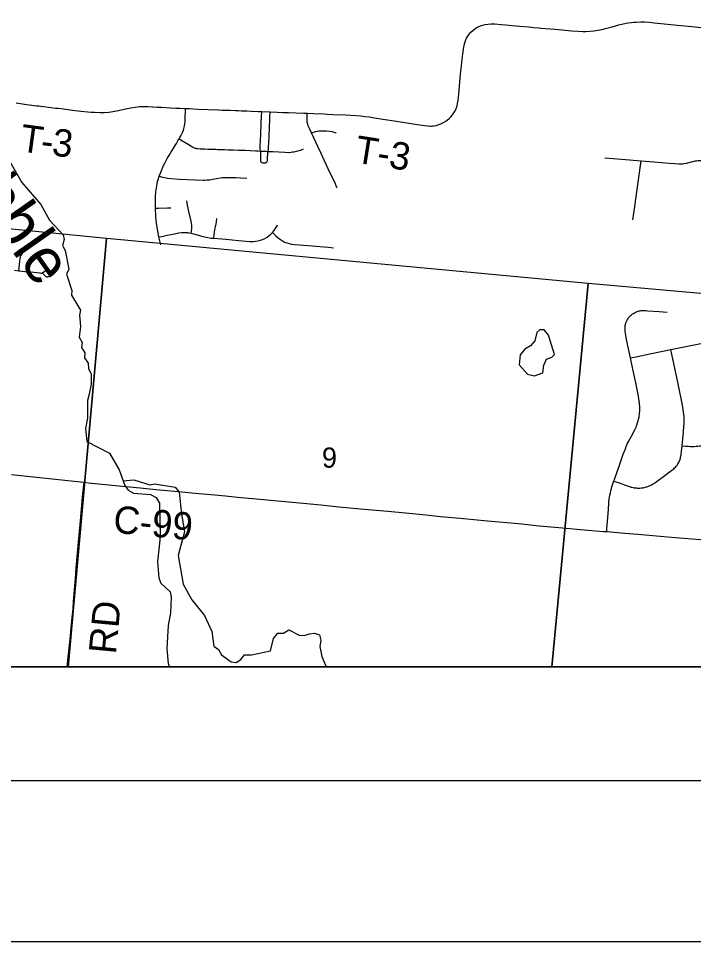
# Model space of a CAD drawing. Extents: x 0 to 1134, y 0 to 440.
# Drawn here: x 288.4 to 330.5, y 0 to 57.5 of the extents above; entities that cross this region are included whole.
import ezdxf

# ---------------------------------------------------------------- set-up
doc = ezdxf.new("R2010")
doc.units = 0
for name, color, linetype in [('GM_X_City_Street', 7, 'Continuous'), ('GM_X_County_Road', 7, 'Continuous'), ('GM_X_County_Road_Text', 7, 'Continuous'), ('GM_X_Major_River', 7, 'Continuous'), ('GM_X_Minor_Lake', 7, 'Continuous'), ('GM_X_Minor_River', 7, 'Continuous'), ('GM_X_Minor_River_Text', 7, 'Continuous'), ('GM_X_Section_Text', 7, 'Continuous'), ('GM_X_Township_Road', 7, 'Continuous'), ('GM_X_Township_Road_Text', 7, 'Continuous'), ('GM_X_Unincorporated', 7, 'Continuous'), ('SH_Border', 7, 'Continuous'), ('SH_Cut_Line', 7, 'Continuous'), ('SH_Text', 7, 'Continuous')]:
    doc.layers.add(name, color=color, linetype=linetype)

msp = doc.modelspace()

# ---------------------------------------------------------------- linework, layer by layer
at = {"layer": 'GM_X_City_Street'}
for points in [[(297.296, 43.386), (297.25, 43.555), (297.208, 43.71), (297.172, 43.877), (297.147, 43.99), (297.098, 44.268), (297.048, 44.598), (297.013, 44.899), (296.989, 45.15), (296.966, 45.661), (296.957, 45.995), (296.96, 46.214), (296.966, 46.389), (296.986, 46.684), (297.016, 46.947), (297.06, 47.193), (297.092, 47.327), (297.124, 47.453), (297.197, 47.669), (297.247, 47.8), (297.29, 47.912), (297.346, 48.055), (297.413, 48.215), (297.469, 48.335), (297.536, 48.47), (297.606, 48.607), (297.688, 48.759), (297.749, 48.858), (297.808, 48.958), (297.875, 49.063), (297.919, 49.133), (298, 49.27), (298.185, 49.571), (298.263, 49.708), (298.38, 49.898), (298.431, 49.981), (298.485, 50.071), (298.544, 50.179), (298.588, 50.267), (298.646, 50.386), (298.702, 50.538), (298.728, 50.632), (298.749, 50.708), (298.769, 50.807), (298.786, 50.907), (298.805, 51.073), (298.813, 51.213), (298.818, 51.35), (298.821, 51.727), (298.823, 51.882)], [(303.495, 49.225), (303.487, 49.352), (303.487, 49.463), (303.506, 49.978), (303.517, 50.216), (303.521, 50.335), (303.526, 50.446), (303.535, 50.767), (303.541, 50.896), (303.549, 51.079), (303.553, 51.163), (303.558, 51.225), (303.565, 51.388), (303.577, 51.687)], [(303.971, 49.209), (303.997, 49.355), (304.002, 49.402), (304.006, 49.466), (304.01, 49.559), (304.015, 49.673), (304.021, 49.799), (304.034, 50.042), (304.051, 50.345), (304.058, 50.484), (304.063, 50.607), (304.067, 50.731), (304.071, 50.884), (304.074, 50.998), (304.084, 51.217), (304.091, 51.382), (304.095, 51.666)], [(308.278, 46.934), (308.264, 46.968), (308.105, 47.328), (307.831, 47.901), (307.272, 49.082), (307.064, 49.52), (306.675, 50.353), (306.566, 50.586), (306.481, 50.79), (306.441, 50.912), (306.415, 51.036), (306.403, 51.164), (306.404, 51.329), (306.404, 51.579)], [(306.675, 50.353), (306.956, 50.442), (307.045, 50.47), (307.137, 50.486), (307.249, 50.492), (307.399, 50.492), (307.606, 50.484), (307.83, 50.464), (307.959, 50.442), (308.067, 50.409), (308.187, 50.357), (308.221, 50.34)], [(298.431, 49.981), (298.509, 49.939), (298.605, 49.888), (298.988, 49.648), (299.222, 49.51), (299.314, 49.46), (299.38, 49.431), (299.425, 49.413), (299.474, 49.401), (299.526, 49.391), (299.602, 49.381), (299.748, 49.369), (299.886, 49.364), (300.025, 49.359), (300.212, 49.354), (300.343, 49.349), (300.457, 49.347), (300.573, 49.342), (300.728, 49.337), (300.844, 49.334), (301.017, 49.329), (301.269, 49.317), (301.484, 49.31), (301.822, 49.3), (302.126, 49.29), (302.55, 49.273), (302.866, 49.258), (303.194, 49.24), (303.341, 49.233), (303.495, 49.225), (303.632, 49.221), (303.857, 49.213), (303.971, 49.209), (304.276, 49.194), (305.02, 49.152), (305.243, 49.148), (305.409, 49.159), (305.496, 49.169), (305.59, 49.184), (305.752, 49.214), (305.859, 49.241), (305.996, 49.29), (306.047, 49.309), (306.18, 49.367)], [(303.495, 49.225), (303.501, 49.152), (303.505, 49.073), (303.503, 48.977), (303.499, 48.849), (303.497, 48.774), (303.494, 48.697), (303.494, 48.63), (303.497, 48.603), (303.503, 48.584), (303.516, 48.564), (303.53, 48.549), (303.549, 48.532), (303.566, 48.523), (303.599, 48.508), (303.642, 48.496), (303.68, 48.492), (303.726, 48.489), (303.77, 48.492), (303.798, 48.495), (303.829, 48.503), (303.86, 48.519), (303.887, 48.538), (303.916, 48.578), (303.926, 48.607), (303.93, 48.636), (303.938, 48.747), (303.953, 49.089), (303.956, 49.13), (303.962, 49.171), (303.971, 49.209)], [(297.197, 47.669), (297.393, 47.608), (297.531, 47.572), (297.62, 47.552), (297.719, 47.536), (297.941, 47.515), (298.461, 47.486), (299.428, 47.444), (299.931, 47.425), (300.03, 47.423), (300.154, 47.427), (300.339, 47.443), (300.542, 47.474), (300.998, 47.563), (301.127, 47.58), (301.222, 47.586), (301.35, 47.591), (301.946, 47.579), (302.262, 47.566), (302.647, 47.547)], [(299.188, 44.113), (299.21, 44.253), (299.228, 44.38), (299.231, 44.437), (299.23, 44.489), (299.218, 44.617), (299.179, 44.855), (299.066, 45.384), (298.965, 45.861), (298.908, 46.135)], [(296.966, 45.661), (297.153, 45.666), (297.708, 45.683), (297.913, 45.687)], [(300.603, 43.797), (300.619, 44.007), (300.632, 44.177), (300.658, 44.345), (300.698, 44.508), (300.749, 44.705), (300.767, 44.812), (300.779, 45.018)], [(297.172, 43.877), (297.349, 43.915), (297.691, 43.987), (298.148, 44.083), (298.386, 44.127), (298.58, 44.155), (298.724, 44.165), (298.846, 44.163), (298.957, 44.155), (299.022, 44.144), (299.188, 44.113), (299.335, 44.074), (299.853, 43.921), (300.014, 43.88), (300.112, 43.858), (300.231, 43.837), (300.415, 43.813), (300.603, 43.797), (301.343, 43.735), (302.142, 43.663), (302.86, 43.602), (302.971, 43.597), (303.067, 43.598), (303.195, 43.608), (303.339, 43.633), (303.499, 43.675), (303.637, 43.725), (303.769, 43.788), (303.911, 43.873), (304.045, 43.969), (304.143, 44.052), (304.253, 44.165), (304.352, 44.284), (304.463, 44.45), (304.533, 44.568), (304.566, 44.638)], [(304.253, 44.165), (304.396, 44.019), (304.46, 43.952), (304.627, 43.804), (304.745, 43.714), (304.871, 43.634), (305.002, 43.564), (305.14, 43.509), (305.283, 43.467), (305.357, 43.449), (305.429, 43.438), (305.614, 43.416), (306.466, 43.342), (307.208, 43.28), (307.745, 43.233), (308.059, 43.204)], [(288.449, 41.771), (288.47, 41.948), (288.492, 42.175), (288.528, 42.506), (288.538, 42.573), (288.544, 42.616), (288.561, 42.67), (288.582, 42.716), (288.606, 42.752), (288.641, 42.795), (288.687, 42.854), (288.704, 42.887), (288.713, 42.923), (288.714, 42.96), (288.708, 42.997), (288.693, 43.031), (288.67, 43.06), (288.639, 43.081), (288.604, 43.092), (288.566, 43.095), (288.524, 43.088), (288.496, 43.074), (288.467, 43.05), (288.446, 43.019), (288.438, 43.002), (288.432, 42.947), (288.436, 42.922), (288.447, 42.893), (288.47, 42.856), (288.498, 42.82), (288.568, 42.738)], [(288.175, 41.801), (288.449, 41.771), (288.508, 41.765), (288.971, 41.712), (289.38, 41.676), (289.749, 41.638), (289.826, 41.63), (289.878, 41.623), (289.904, 41.618), (289.935, 41.605), (289.961, 41.587), (290.011, 41.532), (290.061, 41.474), (290.1, 41.437), (290.138, 41.414), (290.155, 41.406), (290.179, 41.399), (290.211, 41.395), (290.231, 41.395), (290.254, 41.398), (290.283, 41.408), (290.306, 41.419), (290.33, 41.434), (290.352, 41.45), (290.372, 41.47), (290.391, 41.49), (290.41, 41.522), (290.422, 41.557), (290.425, 41.594), (290.422, 41.622), (290.417, 41.649), (290.402, 41.683), (290.391, 41.7), (290.354, 41.74), (290.328, 41.756), (290.306, 41.767), (290.28, 41.776), (290.252, 41.78), (290.222, 41.782), (290.196, 41.778), (290.171, 41.77), (290.136, 41.756), (290.104, 41.74), (289.912, 41.633)]]:
    msp.add_lwpolyline(points, dxfattribs=at)
at = {"layer": 'GM_X_County_Road'}
for points in [[(287.992, 29.088), (292.286, 28.631), (292.517, 28.602)], [(292.517, 28.602), (292.78, 28.572), (294.467, 28.399), (296.008, 28.26), (296.991, 28.161), (297.695, 28.096), (298.382, 28.035), (299.66, 27.91), (300.661, 27.816), (301.328, 27.751), (302.07, 27.681), (303.239, 27.575), (306.152, 27.296), (307.265, 27.19), (308.378, 27.081), (309.733, 26.953), (311.44, 26.796), (313.408, 26.612), (314.168, 26.53), (314.71, 26.475), (315.947, 26.362), (317.633, 26.202), (319.58, 26.026), (320.859, 25.898), (322.083, 25.783), (323.902, 25.621), (324.868, 25.544), (325.072, 25.526)], [(325.072, 25.526), (326.204, 25.427), (327.003, 25.369), (328.396, 25.254), (329.362, 25.171), (330.383, 25.088), (331.944, 24.961), (333.059, 24.874), (334.47, 24.752), (335.148, 24.697)]]:
    msp.add_lwpolyline(points, dxfattribs=at)
at = {"layer": 'GM_X_Major_River'}
for points in [[(261.437, 17.107), (291.515, 17.107), (293.905, 43.779), (264.585, 46.664)], [(291.515, 17.107), (321.649, 17.107), (323.909, 40.986), (293.905, 43.779)], [(321.649, 17.107), (352.406, 17.107), (354.289, 38.278), (323.909, 40.986)]]:
    msp.add_lwpolyline(points, close=True, dxfattribs=at)
at = {"layer": 'GM_X_Minor_Lake'}
for points in [[(321.446, 37.771), (321.18, 38.084), (320.897, 38.101), (320.711, 37.923), (320.588, 37.413), (320.321, 37.1), (319.976, 36.891), (319.685, 36.533), (319.605, 35.909), (320.127, 35.329), (320.568, 35.24), (321.082, 35.423), (321.148, 35.888), (321.315, 36.271), (321.646, 36.389), (321.809, 36.568)], [(321.809, 36.568), (321.446, 37.771)]]:
    msp.add_lwpolyline(points, dxfattribs=at)
at = {"layer": 'GM_X_Minor_River'}
for points in [[(287.65, 48.967), (288.627, 47.274), (289.815, 45.896), (290.352, 44.917), (291.208, 44.012), (291.282, 43.715), (291.162, 43.353), (291.326, 43.042), (291.564, 41.877), (291.41, 41.562), (291.742, 40.553), (291.725, 40.258), (292.286, 39.313), (292.235, 39.018), (292.3, 38.3), (292.207, 37.63), (292.394, 37.308), (292.343, 37.002), (292.552, 36.656), (292.545, 36.349), (292.766, 36.014), (292.793, 35.672), (292.946, 35.362), (292.956, 34.701), (292.817, 33.999), (292.732, 33.693), (292.733, 32.589), (292.607, 31.943), (292.682, 31.145), (294.087, 30.421), (294.702, 29.384), (295.046, 28.409), (295.267, 28.108), (295.593, 27.931), (296.659, 27.84), (296.996, 27.651), (297.216, 27.294), (297.249, 25.517), (297.227, 24.994), (297.087, 23.642), (297.17, 22.65), (297.3, 22.328), (297.879, 21.769), (297.941, 21.472), (297.899, 20.471), (297.747, 19.677)], [(294.947, 28.689), (295.61, 28.762), (296.602, 28.445), (296.922, 28.507), (298.178, 28.287), (298.433, 27.985), (298.576, 26.605), (298.77, 25.519), (298.378, 24.048), (298.683, 22.265), (299.22, 21.275), (300.019, 20.313), (300.476, 19.313), (300.594, 18.399), (300.885, 18.177), (301.072, 17.854), (301.676, 17.42), (301.993, 17.368), (302.281, 17.556), (302.514, 17.858), (302.934, 17.861), (304.131, 18.109), (304.316, 18.868), (304.584, 19.204), (304.936, 19.208), (305.258, 19.418), (305.91, 19.074), (306.227, 19.056), (306.547, 19.163), (306.866, 19.202), (307.182, 19.093), (307.266, 18.773), (307.19, 18.376), (307.326, 17.758), (307.603, 17.107)], [(297.747, 19.677), (297.673, 18.244), (297.757, 17.308), (297.828, 17.107)]]:
    msp.add_lwpolyline(points, dxfattribs=at)
at = {"layer": 'GM_X_Township_Road'}
for points in [[(314.129, 50.784), (314.211, 50.789), (314.329, 50.803), (314.464, 50.829), (314.602, 50.875), (314.745, 50.926), (314.865, 50.982), (315.013, 51.067), (315.137, 51.153), (315.254, 51.249), (315.361, 51.357), (315.458, 51.474), (315.544, 51.598), (315.619, 51.73), (315.69, 51.885), (315.747, 52.045), (315.783, 52.192), (315.813, 52.378), (315.854, 52.787), (315.874, 52.991), (315.94, 53.77), (315.989, 54.233), (315.998, 54.325), (316.063, 54.955), (316.099, 55.288), (316.14, 55.582), (316.187, 55.818), (316.227, 55.96), (316.275, 56.098), (316.344, 56.248), (316.426, 56.391), (316.51, 56.511), (316.605, 56.622), (316.722, 56.738), (316.806, 56.808), (316.942, 56.9), (317.071, 56.968), (317.206, 57.026), (317.362, 57.077), (317.505, 57.11), (317.687, 57.138), (317.87, 57.152), (318.099, 57.145), (318.497, 57.118), (318.774, 57.093), (319.385, 57.032), (320.187, 56.959), (320.386, 56.941), (320.516, 56.927), (320.85, 56.898), (320.96, 56.889), (321.85, 56.81), (322.278, 56.77), (322.887, 56.716), (323.294, 56.687), (323.572, 56.68), (323.778, 56.683), (324.021, 56.692), (324.269, 56.713), (324.515, 56.749), (324.773, 56.796), (324.991, 56.85), (325.404, 56.969), (325.833, 57.09), (326.086, 57.148), (326.378, 57.203), (326.616, 57.235), (326.768, 57.249), (326.894, 57.258), (327.19, 57.27), (327.412, 57.266), (327.711, 57.245), (328.023, 57.217), (329.469, 57.073), (330.377, 56.981), (331.342, 56.887)], [(288.292, 52.227), (288.81, 52.155), (289.548, 52.053), (289.714, 52.034), (289.826, 52.021), (290.454, 51.944), (290.731, 51.909), (290.897, 51.893), (291.079, 51.872), (291.798, 51.78), (292.316, 51.715), (292.742, 51.671), (292.955, 51.654), (293.17, 51.642), (293.505, 51.633), (293.767, 51.637), (294.047, 51.657), (294.306, 51.692), (294.655, 51.757), (295.091, 51.854), (295.435, 51.928), (295.689, 51.97), (295.834, 51.986), (295.964, 51.998), (296.134, 52.006), (296.189, 52.006)], [(296.189, 52.006), (296.328, 52.006), (296.479, 51.998), (296.765, 51.98), (296.795, 51.978)], [(296.795, 51.978), (297.062, 51.963), (297.327, 51.951), (297.627, 51.937), (297.901, 51.923), (298.236, 51.909), (298.266, 51.908)], [(298.266, 51.908), (298.504, 51.899), (298.823, 51.882)], [(298.823, 51.882), (299.08, 51.868), (299.601, 51.844), (300.887, 51.794), (301.111, 51.784), (301.614, 51.765), (301.949, 51.751), (302.117, 51.746), (302.311, 51.739), (302.657, 51.724), (302.918, 51.712), (303.347, 51.695), (303.514, 51.69), (303.577, 51.687)], [(303.577, 51.687), (304.095, 51.666), (304.539, 51.648), (304.874, 51.637), (305.249, 51.625), (306.178, 51.587), (306.404, 51.579)], [(306.404, 51.579), (306.44, 51.577), (306.812, 51.564), (307.464, 51.541), (307.649, 51.531), (308.006, 51.514), (308.806, 51.479)], [(308.806, 51.479), (309.102, 51.466), (309.752, 51.415)], [(309.752, 51.415), (310.007, 51.387), (310.295, 51.349), (310.602, 51.305), (311.118, 51.222), (311.984, 51.093), (313.143, 50.903), (313.716, 50.822), (313.935, 50.796), (314.048, 50.787), (314.129, 50.784)], [(324.943, 48.813), (325.997, 48.732), (327.218, 48.626)], [(326.693, 44.951), (326.818, 45.77), (327.058, 47.427), (327.218, 48.626)], [(327.218, 48.626), (328.001, 48.558), (328.966, 48.471), (329.301, 48.446), (329.563, 48.429), (329.647, 48.427), (329.727, 48.429), (329.796, 48.435), (329.864, 48.445), (330.031, 48.478), (330.357, 48.561), (330.463, 48.587), (330.573, 48.612), (330.653, 48.626), (330.736, 48.637), (330.811, 48.643), (330.882, 48.646), (330.961, 48.646), (331.047, 48.641), (331.118, 48.634), (331.188, 48.626), (331.446, 48.59)], [(326.551, 36.351), (326.332, 37.386), (326.243, 37.861), (326.226, 37.981), (326.214, 38.081), (326.21, 38.132), (326.208, 38.189), (326.21, 38.253), (326.217, 38.316), (326.224, 38.37), (326.235, 38.423), (326.247, 38.467), (326.261, 38.51), (326.287, 38.582), (326.316, 38.645), (326.34, 38.693), (326.366, 38.742), (326.4, 38.798), (326.436, 38.848), (326.462, 38.882), (326.494, 38.917), (326.537, 38.961), (326.585, 39.006), (326.631, 39.044), (326.685, 39.085), (326.733, 39.116), (326.792, 39.154), (326.846, 39.182), (326.906, 39.21), (326.961, 39.232), (327.02, 39.253), (327.083, 39.272), (327.145, 39.284), (327.209, 39.294), (327.275, 39.3), (327.34, 39.301), (327.403, 39.301), (327.51, 39.294), (327.606, 39.286), (328.33, 39.23), (328.832, 39.192)], [(329.067, 36.861), (330.093, 37.078), (330.931, 37.251), (332.165, 37.499)], [(326.551, 36.351), (326.993, 36.442), (327.758, 36.595), (329.067, 36.861)], [(329.767, 30.871), (329.843, 31.73), (329.876, 32.1), (329.885, 32.238), (329.89, 32.396), (329.891, 32.506), (329.889, 32.618), (329.884, 32.72), (329.875, 32.821), (329.859, 32.964), (329.839, 33.115), (329.815, 33.258), (329.787, 33.408), (329.51, 34.739), (329.067, 36.861)], [(325.504, 28.677), (325.796, 29.482), (326.1, 30.343), (326.229, 30.692), (326.281, 30.823), (326.326, 30.932), (326.37, 31.03), (326.427, 31.146), (326.604, 31.476), (326.817, 31.869), (326.858, 31.956), (326.896, 32.039), (326.928, 32.118), (326.963, 32.215), (326.993, 32.314), (327.028, 32.431), (327.056, 32.538), (327.08, 32.65), (327.095, 32.729), (327.108, 32.818), (327.117, 32.906), (327.124, 33.005), (327.128, 33.106), (327.128, 33.212), (327.126, 33.326), (327.118, 33.456), (327.11, 33.543), (327.098, 33.643), (327.075, 33.792), (327.046, 33.956), (326.878, 34.797), (326.693, 35.653), (326.551, 36.351)], [(329.767, 30.871), (329.976, 30.853), (330.168, 30.84), (330.264, 30.836), (330.402, 30.833), (330.521, 30.836), (330.642, 30.842), (330.75, 30.851), (330.855, 30.862), (330.955, 30.876), (331.075, 30.895), (331.563, 30.989), (331.945, 31.07), (332.845, 31.263), (333.184, 31.331), (333.411, 31.375)], [(325.504, 28.677), (325.965, 28.517), (326.17, 28.444), (326.481, 28.332), (326.573, 28.305), (326.64, 28.286), (326.712, 28.27), (326.78, 28.259), (326.845, 28.25), (326.915, 28.245), (326.989, 28.242), (327.067, 28.24), (327.136, 28.243), (327.211, 28.246), (327.275, 28.254), (327.338, 28.263), (327.406, 28.278), (327.476, 28.296), (327.548, 28.318), (327.62, 28.342), (327.703, 28.373), (327.777, 28.405), (327.853, 28.441), (327.918, 28.475), (327.997, 28.522), (328.068, 28.567), (328.15, 28.624), (328.597, 28.958), (328.984, 29.249), (329.084, 29.322), (329.13, 29.356), (329.178, 29.393), (329.242, 29.447), (329.301, 29.502), (329.344, 29.546), (329.39, 29.595), (329.43, 29.645), (329.468, 29.695), (329.502, 29.748), (329.535, 29.804), (329.567, 29.862), (329.596, 29.92), (329.622, 29.98), (329.641, 30.036), (329.66, 30.101), (329.675, 30.161), (329.688, 30.228), (329.7, 30.299), (329.71, 30.359), (329.767, 30.871)], [(291.863, 21.168), (291.901, 21.657), (291.97, 22.604), (292.023, 23.254), (292.106, 24.181), (292.148, 24.646), (292.285, 26.205), (292.44, 27.893), (292.517, 28.602)], [(325.072, 25.526), (325.085, 25.709), (325.153, 26.639), (325.198, 27.251), (325.211, 27.386), (325.227, 27.528), (325.248, 27.675), (325.269, 27.802), (325.295, 27.935), (325.325, 28.074), (325.357, 28.205), (325.39, 28.324), (325.428, 28.45), (325.467, 28.572), (325.504, 28.677)], [(291.454, 17.107), (291.515, 17.708), (291.637, 18.837), (291.713, 19.541), (291.78, 20.172), (291.828, 20.71), (291.863, 21.168)]]:
    msp.add_lwpolyline(points, dxfattribs=at)
at = {"layer": 'GM_X_Unincorporated'}
msp.add_lwpolyline([(131, 17.107), (352.355, 17.107)], dxfattribs=at)
at = {"layer": 'SH_Border'}
msp.add_lwpolyline([(30, 430), (670, 430), (670, 10), (30, 10)], close=True, dxfattribs=at)
at = {"layer": 'SH_Cut_Line'}
msp.add_lwpolyline([(0, 0), (680, 0), (680, 440), (0, 440)], close=True, dxfattribs=at)
msp.add_lwpolyline([(131, 17.107), (535.445, 17.107)], dxfattribs=at)
at = {"layer": 'SH_Text'}
msp.add_lwpolyline([(131, 425.107), (539, 425.107), (539, 17.107), (131, 17.107)], close=True, dxfattribs=at)

# ---------------------------------------------------------------- texts
at = {"layer": 'GM_X_County_Road_Text'}
msp.add_text('C-99', height=1.7045, rotation=354.25764, dxfattribs=at).set_placement((294.277, 25.474))
at = {"layer": 'GM_X_Minor_River_Text'}
msp.add_text('Hebble', height=2.841, rotation=304.9632, dxfattribs=at).set_placement((282.757, 50.495))
at = {"layer": 'GM_X_Section_Text'}
msp.add_text('9', height=1.256, rotation=0.00001, dxfattribs=at).set_placement((307.332, 29.509))
at = {"layer": 'GM_X_Township_Road_Text'}
for s, height, rotation, p in [('T', 1.705, 352.27961, (288.465, 49.22)), ('3', 1.705, 353.30615, (290.457, 48.961)), ('T-3', 1.7045, 351.00097, (309.317, 48.523)), ('-', 1.705, 353.19836, (289.758, 49.045)), ('RD', 1.7045, 84.67555, (294.498, 17.86))]:
    msp.add_text(s, height=height, rotation=rotation, dxfattribs=at).set_placement(p)

doc.saveas('drawing.dxf')
